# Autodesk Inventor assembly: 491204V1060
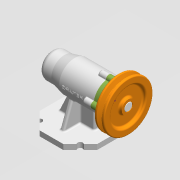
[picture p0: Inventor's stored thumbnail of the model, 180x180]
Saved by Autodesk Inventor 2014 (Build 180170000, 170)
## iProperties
Created: 2019-12
Part Number: 491204V1060
Document SubType Name: Assembly
Designer: NET
Author: NET
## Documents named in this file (12)
- C:\Users\NET\Desktop\491204V1060.iam
- C:\Users\NET\Desktop\조보민\12.ipt
- C:\Users\NET\Desktop\조보민\베어링 51202.ipt
- C:\Users\NET\Desktop\조보민\어댑터슬리브.ipt
- C:\Users\NET\Desktop\조보민\볼트 M4.ipt
- C:\Users\NET\Desktop\조보민\축.ipt
- C:\Users\NET\Desktop\조보민\베어링 6004.ipt
- C:\Users\NET\Desktop\조보민\커버.ipt
- C:\Users\NET\Desktop\조보민\오일 실.ipt
- C:\Users\NET\Desktop\조보민\키 5 x 5 x 16.ipt
- C:\Users\NET\Desktop\조보민\V벨트풀리.ipt
- C:\Users\NET\Desktop\조보민\멈춤나사 M3.ipt
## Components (2 placed, 2 different names)
1. 12:1
2. V벨트풀리:1
